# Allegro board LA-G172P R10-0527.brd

Outline 293.2 x 85.85 mm; copper layers: TOP, GND1, IN1, GND2, VCC, IN2, GND3, IN3, GND4, BOTTOM. Coordinates in mm from the lower left corner of the outline.

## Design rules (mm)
net group CB: nets CBN CBP
net group CHG_CSI: nets CHG_CSIN CHG_CSIP
net group CHG_CSO: nets CHG_CSON CHG_CSOP
net group CLK_PCIE_P1: nets CLK_PCIE_N1 CLK_PCIE_P1
net group CLK_PCIE_P1_R: nets CLK_PCIE_N1_R CLK_PCIE_P1_R
net group CLK_SMB: nets CLK_SMB DAT_SMB
net group CLK_TP_SIO_I2C_DAT: nets CLK_TP_SIO_I2C_DAT DAT_TP_SIO_I2C_CLK
net group DDR_A_CLK: nets DDR_A_CLK DDR_A_CLK#
net group DDR_B_CLK: nets DDR_B_CLK DDR_B_CLK#
net group DDR_C_CLK: nets DDR_C_CLK DDR_C_CLK#
net group DDR_C_DQS0: nets DDR_C_DQS0 DDR_C_DQS#0
net group DDR_C_DQS1: nets DDR_C_DQS1 DDR_C_DQS#1
net group DDR_C_DQS2: nets DDR_C_DQS2 DDR_C_DQS#2
net group DDR_C_DQS3: nets DDR_C_DQS3 DDR_C_DQS#3
net group DDR_D_CLK: nets DDR_D_CLK DDR_D_CLK#
net group DDR_D_DQS0: nets DDR_D_DQS0 DDR_D_DQS#0
net group DDR_D_DQS1: nets DDR_D_DQS1 DDR_D_DQS#1
net group DDR_D_DQS2: nets DDR_D_DQS2 DDR_D_DQS#2
net group DDR_D_DQS3: nets DDR_D_DQS3 DDR_D_DQS#3
net group DDRA_CKE: nets DDR_A_CKE0 DDR_A_CKE1
net group DDRA_CTL: nets DDR_A_CS#0 DDR_A_CS#1
net group DDRB_CKE: nets DDR_B_CKE0 DDR_B_CKE1
net group DDRB_CTL: nets DDR_B_CS#0 DDR_B_CS#1
net group DDRC_CKE: nets DDR_C_CKE0 DDR_C_CKE1
net group DDRC_CTL: nets DDR_C_CS#0 DDR_C_CS#1
net group DDRD_CKE: nets DDR_D_CKE0 DDR_D_CKE1
net group DDRD_CTL: nets DDR_D_CS#0 DDR_D_CS#1
net group DIFFPAIR50: nets I2C3_PD_R_CLK_R I2C3_PD_R_DAT_R
net group EDP_AUXP_CONN: nets EDP_AUXN_CONN EDP_AUXP_CONN
net group EDP_TXP0_CONN: nets EDP_TXN0_CONN EDP_TXP0_CONN
net group EDP_TXP1_CONN: nets EDP_TXN1_CONN EDP_TXP1_CONN
net group EDP_TXP2_CONN: nets EDP_TXN2_CONN EDP_TXP2_CONN
net group EDP_TXP3_CONN: nets EDP_TXN3_CONN EDP_TXP3_CONN
net group I2C1_PD_L_CLK: nets I2C1_PD_L_CLK I2C1_PD_L_DAT
net group I2C1_PD_R_CLK: nets I2C1_PD_R_CLK I2C1_PD_R_DAT
net group I2C1_SCK_TP: nets I2C1_SCK_TP I2C1_SDA_TP
net group I2C2_PD_L_CLK: nets I2C2_PD_L_CLK I2C2_PD_L_DAT
net group I2C2_PD_R_CLK: nets I2C2_PD_R_CLK I2C2_PD_R_DAT
net group I2C_3_SCL_UFCAM: nets I2C_3_SCL_UFCAM I2C_3_SDA_UFCAM
net group I2C_3_SCL_UFCAM_R: nets I2C_3_SCL_UFCAM_R I2C_3_SDA_UFCAM_R
net group IMVP_SMBCLK: nets IMVP_SMBCLK IMVP_SMBDAT
net group IMVP_SMBCLK_VR: nets IMVP_SMBCLK_VR IMVP_SMBDAT_VR
net group ISH_I2C0_SCL: nets ISH_I2C0_SCL ISH_I2C0_SDA
net group ISH_I2C1_SCL: nets ISH_I2C1_SCL ISH_I2C1_SDA
net group ISH_I2C1_SCL_R: nets ISH_I2C1_SCL_R ISH_I2C1_SDA_R
net group MIPI60_CFG_STB0_D: nets MIPI60_CFG_STB0_DN MIPI60_CFG_STB0_DP
net group MIPI60_CFG_STB1_D: nets MIPI60_CFG_STB1_DN MIPI60_CFG_STB1_DP
net group N20151664: nets N20151644 N20151664
net group PCH_DMIC_CLK12: nets PCH_DMIC_CLK12 PCH_DMIC_DATA12
net group PCIE_PRX_DTX_P13: nets PCIE_PRX_DTX_N13 PCIE_PRX_DTX_P13
net group PCIE_PRX_DTX_P14: nets PCIE_PRX_DTX_N14 PCIE_PRX_DTX_P14
net group PCIE_PTX_C_DRX_P13: nets PCIE_PTX_C_DRX_N13 PCIE_PTX_C_DRX_P13
net group PCIE_PTX_C_DRX_P14: nets PCIE_PTX_C_DRX_N14 PCIE_PTX_C_DRX_P14
net group PCIE_PTX_DRX_P13: nets PCIE_PTX_DRX_N13 PCIE_PTX_DRX_P13
net group PCIE_PTX_DRX_P14: nets PCIE_PTX_DRX_N14 PCIE_PTX_DRX_P14
net group PCIE_RCOMP: nets PCIE_RCOMPN PCIE_RCOMPP
net group PECI: nets PCH_PCIE_WAKE# PCIE_WAKE#
net group REM_DIODE1: nets REM_DIODE1_N REM_DIODE1_P
net group REM_DIODE4: nets REM_DIODE4_N REM_DIODE4_P
net group SMB_CLK: nets SMB_CLK SMB_DATA
net group SMB_CLK_MIPI60: nets SMB_CLK_MIPI60 SMB_DATA_MIPI60
net group SML0_SMBCLK: nets SML0_SMBCLK SML0_SMBDATA
net group SML0B_SMBCLK: nets SML0B_SMBCLK SML0B_SMBDATA
net group SML1_SMBCLK: nets SML1_SMBCLK SML1_SMBDATA
net group SML1_SMBCLK_R: nets SML1_SMBCLK_R SML1_SMBDATA_R
net group TAP_SMBCLK: nets TAP_SMBCLK TAP_SMBDAT
net group TAP_SMBCLK_R: nets TAP_SMBCLK_R TAP_SMBDAT_R
net group TBT_0_TRX_C_RD_DTX_0: nets TBT_0_TRX_C_RD_DTX_N0 TBT_0_TRX_C_RD_DTX_P0
net group TBT_0_TRX_C_RD_DTX_1: nets TBT_0_TRX_C_RD_DTX_N1 TBT_0_TRX_C_RD_DTX_P1
net group TBT_0_TRX_RT_DTX_0: nets TBT_0_TRX_RT_DTX_N0 TBT_0_TRX_RT_DTX_P0
net group TBT_0_TRX_RT_DTX_1: nets TBT_0_TRX_RT_DTX_N1 TBT_0_TRX_RT_DTX_P1
net group TBT_0_TTX_C_RD_DRX_0: nets TBT_0_TTX_C_RD_DRX_N0 TBT_0_TTX_C_RD_DRX_P0
net group TBT_0_TTX_C_RD_DRX_1: nets TBT_0_TTX_C_RD_DRX_N1 TBT_0_TTX_C_RD_DRX_P1
net group TBT_0_TTX_CD_DRX_0: nets TBT_0_TTX_CD_DRX_N0 TBT_0_TTX_CD_DRX_P0
net group TBT_0_TTX_CD_DRX_1: nets TBT_0_TTX_CD_DRX_N1 TBT_0_TTX_CD_DRX_P1
net group TBT_2_TRX_C_RD_DTX_0: nets TBT_2_TRX_C_RD_DTX_N0 TBT_2_TRX_C_RD_DTX_P0
net group TBT_2_TRX_C_RD_DTX_1: nets TBT_2_TRX_C_RD_DTX_N1 TBT_2_TRX_C_RD_DTX_P1
net group TBT_2_TRX_RT_DTX_P0: nets TBT_2_TRX_RT_DTX_N0 TBT_2_TRX_RT_DTX_P0
net group TBT_2_TRX_RT_DTX_P1: nets TBT_2_TRX_RT_DTX_N1 TBT_2_TRX_RT_DTX_P1
net group TBT_2_TTX_C_RD_DRX_0: nets TBT_2_TTX_C_RD_DRX_N0 TBT_2_TTX_C_RD_DRX_P0
net group TBT_2_TTX_C_RD_DRX_1: nets TBT_2_TTX_C_RD_DRX_N1 TBT_2_TTX_C_RD_DRX_P1
net group TBT_2_TTX_CD_DRX_P1: nets TBT_2_TTX_CD_DRX_N1 TBT_2_TTX_CD_DRX_P1
net group TBT_L_SMBCLK: nets TBT_L_SMBCLK TBT_L_SMBDAT
net group TBT_R_SMBCLK: nets TBT_R_SMBCLK TBT_R_SMBDAT
net group TCRCOMP_D: nets TCRCOMP_DN TCRCOMP_DP
net group TS_I2C_SCL_R: nets TS_I2C_SCL_R TS_I2C_SDA_R
net group UPD_L_SMBCLK: nets UPD_L_SMBCLK UPD_L_SMBDAT
net group UPD_R_SMBCLK: nets UPD_R_SMBCLK UPD_R_SMBDAT
net group UPD_SMBCLK: nets UPD_SMBCLK UPD_SMBDAT
net group USB20_N10: nets USB20_N10 USB20_P10
net group USB20_N10_R: nets USB20_N10_R USB20_P10_R
net group WOV_DMIC_CLK0: nets WOV_DMIC_CLK0 WOV_DMIC_DATA0
net group 10: nets SPK_-OUT-L+ SPK_-OUT-L- SPK_-OUT-R+ SPK_-OUT-R- SPK_L+ SPK_L- SPK_R+ SPK_R- TBT_L_CC1 TBT_L_CC2 TBT_R_CC1 TBT_R_CC2
net group 12: nets DDR_DRAMRST# DDR_DRAMRST#_R H_CATERR# H_PROCHOT# H_PROCHOT#_R SD_CD# SD_CLK SD_CLK_L SD_CMD SD_CMD_L SD_D2 SD_D2_L SD_D3 SD_D3_L SD_LN0_M SD_LN0_P SD_LN1_M SD_LN1_P SD_RCLK_M SD_RCLK_M_L SD_RCLK_P SD_RCLK_P_L SD_REG2 SP7_SDWP
net group CLK_S: nets MEC_XTAL1 MEC_XTAL2 MEC_XTAL2_R PCH_RTCX1 PCH_RTCX2 PCH_RTCX2_R TBT_L_XTAL_25_IN TBT_L_XTAL_25_IN_R TBT_L_XTAL_25_OUT TBT_L_XTAL_25_OUT_R TBT_R_XTAL_25_IN TBT_R_XTAL_25_IN_R TBT_R_XTAL_25_OUT TBT_R_XTAL_25_OUT_R XTAL_38P4M_IN XTAL_38P4M_IN_CPU XTAL_38P4M_OUT XTAL_38P4M_OUT_CPU
net group CNV: nets CLK_CNV_PRX_DTX_N CLK_CNV_PRX_DTX_P CLK_CNV_PTX_DRX_N CLK_CNV_PTX_DRX_P CNV_PRX_DTX_N0 CNV_PRX_DTX_N1 CNV_PRX_DTX_P0 CNV_PRX_DTX_P1 CNV_PTX_DRX_N0 CNV_PTX_DRX_N1 CNV_PTX_DRX_P0 CNV_PTX_DRX_P1
net group CNV_S: nets CNV_BRI_PRX_DTX CNV_BRI_PRX_R_DTX CNV_BRI_PRX_R_DTX_R CNV_BRI_PTX_DRX CNV_BRI_PTX_R_DRX CNV_RGI_PRX_DTX CNV_RGI_PRX_R_DTX CNV_RGI_PTX_DRX CNV_RGI_PTX_R_DRX CNV_RGI_PTX_R_DRX_R
net group CRITICAL: nets SUSCLK
net group DDR_DQS: nets DDR_A_DQS0 DDR_A_DQS1 DDR_A_DQS2 DDR_A_DQS3 DDR_A_DQS#0 DDR_A_DQS#1 DDR_A_DQS#2 DDR_A_DQS#3 DDR_B_DQS0 DDR_B_DQS1 DDR_B_DQS2 DDR_B_DQS3 DDR_B_DQS#0 DDR_B_DQS#1 DDR_B_DQS#2 DDR_B_DQS#3
net group DDRA_CA: nets DDR_A_CA0 DDR_A_CA1 DDR_A_CA2 DDR_A_CA3 DDR_A_CA4 DDR_A_CA5
net group DDRA_D0: nets DDR_A_D0_0 DDR_A_D0_1 DDR_A_D0_2 DDR_A_D0_3 DDR_A_D0_4 DDR_A_D0_5 DDR_A_D0_6 DDR_A_D0_7
net group DDRA_D1: nets DDR_A_D1_0 DDR_A_D1_1 DDR_A_D1_2 DDR_A_D1_3 DDR_A_D1_4 DDR_A_D1_5 DDR_A_D1_6 DDR_A_D1_7
net group DDRA_D2: nets DDR_A_D2_0 DDR_A_D2_1 DDR_A_D2_2 DDR_A_D2_3 DDR_A_D2_4 DDR_A_D2_5 DDR_A_D2_6 DDR_A_D2_7
net group DDRA_D3: nets DDR_A_D3_0 DDR_A_D3_1 DDR_A_D3_2 DDR_A_D3_3 DDR_A_D3_4 DDR_A_D3_5 DDR_A_D3_6 DDR_A_D3_7
net group DDRB_CA: nets DDR_B_CA0 DDR_B_CA1 DDR_B_CA2 DDR_B_CA3 DDR_B_CA4 DDR_B_CA5
net group DDRB_D0: nets DDR_B_D0_0 DDR_B_D0_1 DDR_B_D0_2 DDR_B_D0_3 DDR_B_D0_4 DDR_B_D0_5 DDR_B_D0_6 DDR_B_D0_7
net group DDRB_D1: nets DDR_B_D1_0 DDR_B_D1_1 DDR_B_D1_2 DDR_B_D1_3 DDR_B_D1_4 DDR_B_D1_5 DDR_B_D1_6 DDR_B_D1_7
net group DDRB_D2: nets DDR_B_D2_0 DDR_B_D2_1 DDR_B_D2_2 DDR_B_D2_3 DDR_B_D2_4 DDR_B_D2_5 DDR_B_D2_6 DDR_B_D2_7
net group DDRB_D3: nets DDR_B_D3_0 DDR_B_D3_1 DDR_B_D3_2 DDR_B_D3_3 DDR_B_D3_4 DDR_B_D3_5 DDR_B_D3_6 DDR_B_D3_7
net group DDRC_CA: nets DDR_C_CA0 DDR_C_CA1 DDR_C_CA2 DDR_C_CA3 DDR_C_CA4 DDR_C_CA5
net group DDRC_D0: nets DDR_C_D0_0 DDR_C_D0_1 DDR_C_D0_2 DDR_C_D0_3 DDR_C_D0_4 DDR_C_D0_5 DDR_C_D0_6 DDR_C_D0_7
net group DDRC_D1: nets DDR_C_D1_0 DDR_C_D1_1 DDR_C_D1_2 DDR_C_D1_3 DDR_C_D1_4 DDR_C_D1_5 DDR_C_D1_6 DDR_C_D1_7
net group DDRC_D2: nets DDR_C_D2_0 DDR_C_D2_1 DDR_C_D2_2 DDR_C_D2_3 DDR_C_D2_4 DDR_C_D2_5 DDR_C_D2_6 DDR_C_D2_7
net group DDRC_D3: nets DDR_C_D3_0 DDR_C_D3_1 DDR_C_D3_2 DDR_C_D3_3 DDR_C_D3_4 DDR_C_D3_5 DDR_C_D3_6 DDR_C_D3_7
net group DDRD_CA: nets DDR_D_CA0 DDR_D_CA1 DDR_D_CA2 DDR_D_CA3 DDR_D_CA4 DDR_D_CA5
net group DDRD_D0: nets DDR_D_D0_0 DDR_D_D0_1 DDR_D_D0_2 DDR_D_D0_3 DDR_D_D0_4 DDR_D_D0_5 DDR_D_D0_6 DDR_D_D0_7
net group DDRD_D1: nets DDR_D_D1_0 DDR_D_D1_1 DDR_D_D1_2 DDR_D_D1_3 DDR_D_D1_4 DDR_D_D1_5 DDR_D_D1_6 DDR_D_D1_7
net group DDRD_D2: nets DDR_D_D2_0 DDR_D_D2_1 DDR_D_D2_2 DDR_D_D2_3 DDR_D_D2_4 DDR_D_D2_5 DDR_D_D2_6 DDR_D_D2_7
net group DDRD_D3: nets DDR_D_D3_0 DDR_D_D3_1 DDR_D_D3_2 DDR_D_D3_3 DDR_D_D3_4 DDR_D_D3_5 DDR_D_D3_6 DDR_D_D3_7
net group EDP: nets EDP_AUXN EDP_AUXP EDP_TXN0 EDP_TXN1 EDP_TXN2 EDP_TXN3 EDP_TXP0 EDP_TXP1 EDP_TXP2 EDP_TXP3
net group ESPI: nets ESPI_CLK ESPI_CLK_5105 ESPI_CS# ESPI_IO0 ESPI_IO0_R ESPI_IO1 ESPI_IO1_R ESPI_IO2 ESPI_IO2_R ESPI_IO3 ESPI_IO3_R ESPI_RESET#
net group HDA: nets HDA_BIT_CLK HDA_BIT_CLK_L HDA_SDIN0 HDA_SDOUT HDA_SDOUT_L HDA_SYNC HDA_SYNC_L
net group I2C: nets I2C3_PD_L_CLK_R I2C3_PD_L_DAT_R I2C_RT_L_SCL I2C_RT_L_SDA I2C_RT_R_SCL I2C_RT_R_SDA TS_I2C_SCL TS_I2C_SDA
net group MIPI: nets MCSI_E_CLKN MCSI_E_CLKP MCSI_E_DN0 MCSI_E_DP0
net group PCIE: nets PCIE_PRX_C_DTX_N3 PCIE_PRX_C_DTX_N9 PCIE_PRX_C_DTX_N10 PCIE_PRX_C_DTX_N11 PCIE_PRX_C_DTX_N12 PCIE_PRX_C_DTX_N16 PCIE_PRX_C_DTX_P3 PCIE_PRX_C_DTX_P9 PCIE_PRX_C_DTX_P10 PCIE_PRX_C_DTX_P11 PCIE_PRX_C_DTX_P12 PCIE_PRX_C_DTX_P16 PCIE_PRX_DTX_N3 PCIE_PRX_DTX_N9 PCIE_PRX_DTX_N10 PCIE_PRX_DTX_N11 PCIE_PRX_DTX_N12 PCIE_PRX_DTX_N16 PCIE_PRX_DTX_P3 PCIE_PRX_DTX_P9 PCIE_PRX_DTX_P10 PCIE_PRX_DTX_P11 PCIE_PRX_DTX_P12 PCIE_PRX_DTX_P16 PCIE_PTX_C_DRX_N3 PCIE_PTX_C_DRX_N9 PCIE_PTX_C_DRX_N10 PCIE_PTX_C_DRX_N11 PCIE_PTX_C_DRX_N12 PCIE_PTX_C_DRX_N16 PCIE_PTX_C_DRX_P3 PCIE_PTX_C_DRX_P9 PCIE_PTX_C_DRX_P10 PCIE_PTX_C_DRX_P11 PCIE_PTX_C_DRX_P12 PCIE_PTX_C_DRX_P16 PCIE_PTX_DRX_N3 PCIE_PTX_DRX_N9 PCIE_PTX_DRX_N10 PCIE_PTX_DRX_N11 PCIE_PTX_DRX_N12 PCIE_PTX_DRX_N16 PCIE_PTX_DRX_P3 PCIE_PTX_DRX_P9 PCIE_PTX_DRX_P10 PCIE_PTX_DRX_P11 PCIE_PTX_DRX_P12 PCIE_PTX_DRX_P16
net group PLAT_CLK: nets CLK_PCIE_N0 CLK_PCIE_N0_R CLK_PCIE_N2 CLK_PCIE_N2_R CLK_PCIE_N4 CLK_PCIE_N4_R CLK_PCIE_P0 CLK_PCIE_P0_R CLK_PCIE_P2 CLK_PCIE_P2_R CLK_PCIE_P4 CLK_PCIE_P4_R
net group PWR: nets +3.3V_EC_PLL +3VALWP +3VS_FP +3VS_TPM +5VALWP +EC_DEBUG_VCC +PECI_VREF +RTC_CELL_VBAT +RTCBATT +RTCVCC +VBATT +VR_CAP
net group RTC: nets PCH_RTCRST#
net group SMB: nets DMIC_CLK12 DMIC_DATA12 PBAT_CHARGER_SMBCLK PBAT_CHARGER_SMBDAT UPD_SMBCLK_Q UPD_SMBDAT_Q
net group SPI: nets PCH_SPI_CLK PCH_SPI_CLK_R PCH_SPI_CLK_TPM SPI_CLK_VROM0
net group SPI_5_15: nets PCH_SPI_CS0# PCH_SPI_CS0#_R PCH_SPI_CS1# PCH_SPI_CS2# PCH_SPI_CS2#_TPM PCH_SPI_IO2 PCH_SPI_IO2_R PCH_SPI_IO3 PCH_SPI_IO3_R PCH_SPI_SI PCH_SPI_SI_R PCH_SPI_SI_TPM PCH_SPI_SO PCH_SPI_SO_R PCH_SPI_SO_TPM SPI_IO2_VROM0 SPI_IO3_VROM0 SPI_SI_VROM0 SPI_SO_VROM0
net group TBT_CONN: nets TBT_0_TTX_C_DRX_N0 TBT_0_TTX_C_DRX_N1 TBT_0_TTX_C_DRX_P0 TBT_0_TTX_C_DRX_P1 TBT_2_TTX_C_DRX_N0 TBT_2_TTX_C_DRX_N1 TBT_2_TTX_C_DRX_P0 TBT_2_TTX_C_DRX_P1 TBT_2_TTX_CD_DRX_N0 TBT_2_TTX_CD_DRX_P0
net group TBT_SOC: nets TBT_0_DP_AUXN TBT_0_DP_AUXN_R TBT_0_DP_AUXP TBT_0_DP_AUXP_R TBT_0_TRX_DTX_N0 TBT_0_TRX_DTX_N1 TBT_0_TRX_DTX_P0 TBT_0_TRX_DTX_P1 TBT_0_TTX_DRX_N0 TBT_0_TTX_DRX_N1 TBT_0_TTX_DRX_P0 TBT_0_TTX_DRX_P1 TBT_2_DP_AUXN TBT_2_DP_AUXN_R TBT_2_DP_AUXP TBT_2_DP_AUXP_R TBT_2_TRX_DTX_N0 TBT_2_TRX_DTX_N1 TBT_2_TRX_DTX_P0 TBT_2_TRX_DTX_P1 TBT_2_TTX_DRX_N0 TBT_2_TTX_DRX_N1 TBT_2_TTX_DRX_P0 TBT_2_TTX_DRX_P1
net group THERMAL: nets REM_DIODE2_N REM_DIODE2_P REM_DIODE3_N REM_DIODE3_P
net group THERMTRIP: nets H_THERMTRIP#
net group USB2.0: nets SW_TBT_L_USB20_N1 SW_TBT_L_USB20_N1_R SW_TBT_L_USB20_N2 SW_TBT_L_USB20_N2_R SW_TBT_L_USB20_P1 SW_TBT_L_USB20_P1_R SW_TBT_L_USB20_P2 SW_TBT_L_USB20_P2_R SW_TBT_R_USB20_N1 SW_TBT_R_USB20_N1_R SW_TBT_R_USB20_N2 SW_TBT_R_USB20_N2_R SW_TBT_R_USB20_P1 SW_TBT_R_USB20_P1_R SW_TBT_R_USB20_P2 SW_TBT_R_USB20_P2_R USB20_N1 USB20_N5 USB20_N5_R USB20_N8 USB20_N9 USB20_P1 USB20_P5 USB20_P5_R USB20_P8 USB20_P9
net group USB3.0: nets USB3_PRX_DTX_N2 USB3_PRX_DTX_P2 USB3_PTX_C_DRX_N2 USB3_PTX_C_DRX_P2 USB3_PTX_DRX_N2 USB3_PTX_DRX_P2
nets with their own width: min track width 0.254; nets +1.8VS_AUDIO +3.3V_ALW_UE1 +3.3V_BAT_LDO +3.3V_TBT_L_ANA +3.3V_TBT_L_FLASH +3.3V_TBT_L_FLASH_R +3.3V_TBT_L_LC +3.3V_TBT_L_SX +3.3V_TBT_R_ANA +3.3V_TBT_R_FLASH +3.3V_TBT_R_FLASH_R +3.3V_TBT_R_LC +3.3V_TBT_R_SX +3.3VA_TBT_L +3.3VA_TBT_R +3V_1.8V_HDA +3V_NB_LID +3V_SPI +3VS_AUDIO +3VS_TS +AVDD1 +DVDD +DVDD_MIC +DVDDIO +SD_VDD2 +V1.05A_BYPASS +VCC1P05_OUTPUT_PLL +VCC1V8_TBT_L_LDO +VCC1V8_TBT_R_LDO +VCCA_CLKLDO_1P8 +VCCDPHY_1P24 +VCCDSW_1P05 +VCCIO_OUT +VCCLDOSTD_OUT_0P85 +VCCPRTC_3P3 +VSS_PLL LDO2_CAP LDO3_CAP N59074258
nets with their own width: min track width 0.297; nets N57957180 N57957195 N57957882 N73546395
nets with their own width: min track width 0.381; nets +3.3V_TBT_L +3.3V_TBT_R HPOL_CONN HPOR_CONN HPOUT-L HPOUT-L_L HPOUT-R HPOUT-R_L LINE2-L LINE2-R MIC2-VREFO-L MIC2-VREFO-R
nets with their own width: min track width 0.508; nets +0.6V_VDDQP +1.1V_MEM +1.8V_3.3V_ALW_VTR3 +1.8V_PRIM +1.8VS +3V_NB_LID_R +3V_PRIM +3VALW +3VALW_DSW +3VS +3VS_SSD +5VALW +5VALWB +5VS_AUDIO +CHG_SRC_20V +RTCVCC_R +SSD_PWR2P +SSD_PWR3P +V1.05A_MIPI60 +V1.05A_VREF_DEBUG +VCC3V3_TBT_L_LDO +VCC3V3_TBT_R_LDO +VIN_3V3_L_TBT +VIN_3V3_R_TBT +VNN_BYPASS B+ GND JUSBC1_GND N73891446
nets with their own width: min track width 0.762; nets +1.05V_VCCST +1.05V_VCCSTG +1.8V_MEM +LCDVDD +SD_VDD1 +TBT_L_SVR_IND +TBT_R_SVR_IND +VCC1.05_OUT_FET +VCC1.05_OUT_PCH +VCC_SFR_OC +VCCST_CPU +VCCSTG_CPU +VCCSTG_OUT +VCCSTG_OUT_LGC
nets with their own width: min track width 1.016; nets +0.9V_TBT_L_LVR +0.9V_TBT_L_SVR +0.9V_TBT_R_LVR +0.9V_TBT_R_SVR +5VBS +5VS +INV_PWR_SRC RING2 RING2_CONN SLEEVE SLEEVE_CONN
nets with their own width: min track width 1.27; nets +VDDQ_MEM
nets with their own width: min track width 1.524; nets +1.1V_MEMP +PVDD
nets with their own width: min track width 1.778; nets +0.6V_VDDQ +3V_5V_CAM_PWR +CAM_PWR
nets with their own width: min track width 2.032; nets +3.3VDX_SSD +3VS_CR +3VS_WLAN +SSD_PWR3 +SSD_PWR_3 +VCC1P8A
nets with their own width: min track width 3.048; nets +1.8V_1.2V_SSD +1.8V_1.2VDX_SSD +CHG_VIN_20V +SSD_PWR2
nets with their own width: min track width 3.556; nets +5VALW_L_TBT +5VALWB_R_TBT +TBT_VBUS_L +TBT_VBUS_L_PD +TBT_VBUS_R +TBT_VBUS_R_PD

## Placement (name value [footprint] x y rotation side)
C1  0.1U_0201_10V6K  [C_0201]  135.16 77.02 90 bottom
C2  0.1U_0201_10V6K  [C_0201]  135.73 77.02 90 bottom
C3  0.1U_0201_10V6K  [C_0201]  136.81 77.02 90 bottom
C4  0.1U_0201_10V6K  [C_0201]  137.38 77.02 90 bottom
C5  0.1U_0201_10V6K  [C_0201]  138.46 77.02 90 bottom
C6  0.1U_0201_10V6K  [C_0201]  139.03 77.02 90 bottom
C7  0.1U_0201_10V6K  [C_0201]  140.05 77.02 90 bottom
C8  0.1U_0201_10V6K  [C_0201]  140.62 77.02 90 bottom
C9  0.1U_0201_10V6K  [C_0201]  134.21 77.02 90 bottom
C10  0.1U_0201_10V6K  [C_0201]  133.64 77.02 90 bottom
C37  1U_0201_6.3V6M  [C_0201]  107.16 69.48 270 top
C38  0.1U_0201_10V6K  [C_0201]  106.74 71.86 0 top
C41  10U_0402_6.3V6M  [C_0402]  106.71 70.97 0 top
C46  0.1U_0201_10V6K  [C_0201]  126.33 83.37 90 bottom
C47  10U_0402_10V6M  [C_0402]  127.1 83.34 90 bottom
C48  33P_0402_50V8J  [C_0402]  127.99 83.34 90 bottom
C49  0.1U_0402_25V6  [C_0402]  98.08 71.14 90 top
C50  1U_0603_25V6K  [C_0603]  99.04 66.83 270 top
C52  0.1U_0402_25V6  [C_0402]  126.4 80.31 0 bottom
C58  0.1U_0402_25V6  [C_0402]  126.25 81.99 0 bottom
C87  0.1U_0402_25V6  [C_0402]  102.02 71.99 0 top
C92  2.2U_0201_6.3V6M  [C_0201]  206.66 61.25 0 bottom
C94  10U_0402_6.3V6M  [C_0402]  207.59 5.84 180 top
C95  0.1U_0201_10V6K  [C_0201]  207.4 6.58 180 top
C96  0.1U_0201_10V6K  [C_0201]  215.22 9.04 0 top
C97  0.1U_0201_10V6K  [C_0201]  212.19 4.46 270 top
C100  0.1U_0201_10V6K  [C_0201]  113.32 3.69 270 bottom
C112  1U_0201_6.3V6M  [C_0201]  177.34 11.15 180 top
C200  0.1U_0201_16V6K  [C_0201]  110.78 3.69 270 bottom
C216  1U_0201_6.3V6M  [C_0201]  205.99 11.87 90 top
C217  2200P_0402_25V7K  [C_0402]  203.55 15.01 90 top
C218  0.1U_0201_10V6K  [C_0201]  201.2 16.52 270 top
C220  0.1U_0201_16V6K  [C_0201]  117.76 3.69 270 bottom
C223  0.1U_0201_10V6K  [C_0201]  172.31 71.39 270 top
C224  2200P_0402_25V7K  [C_0402]  174.47 70.24 90 top
C227  1000P_0402_25V8J  [C_0402]  238.97 18.9 0 top
C229  1U_0201_6.3V6M  [C_0201]  241.24 18.74 180 top
C230  0.1U_0201_10V6K  [C_0201]  237.42 18.77 0 top
C233  0.1U_0201_10V6K  [C_0201]  175.52 71.86 180 top
C234  4700P_0402_16V7K  [C_0402]  67.15 13.38 270 top
C235  1U_0201_6.3V6M  [C_0201]  172.88 65.28 270 top
C237  2200P_0402_25V7K  [C_0402]  175.36 70.24 90 top
C240  1U_0201_6.3V6M  [C_0201]  176.63 65.42 270 top
C243  1U_0201_6.3V6M  [C_0201]  17.74 27.92 225 top
C244  1000P_0402_25V8J  [C_0402]  19.34 23.02 135 top
C245  3300P_0402_25V7K  [C_0402]  42.23 16.67 180 top
C246  1U_0201_10V6M  [C_0201]  45.54 14.64 180 top
C248  0.1U_0201_10V6K  [C_0201]  188.56 53.15 90 top
C252  1U_0201_6.3V6M  [C_0201]  195.13 51.54 0 top
C256  1U_0201_6.3V6M  [C_0201]  68.17 18.35 90 top
C276  0.1U_0201_10V6K  [C_0201]  68.13 11.15 0 top
C277  0.1U_0201_10V6K  [C_0201]  20.94 22.79 45 top
C278  0.1U_0201_10V6K  [C_0201]  41.27 15.47 0 top
C285  0.1U_0201_16V6K  [C_0201]  118.4 3.69 270 bottom
C418  0.1U_0201_10V6K  [C_0201]  128.72 77.99 270 bottom
C419  0.1U_0201_25V6K  [C_0201]  126.66 81.26 0 bottom
C420  0.1U_0201_25V6K  [C_0201]  128.72 83.59 90 bottom
C421  10U_0402_6.3V6M  [C_0402]  207.59 10.84 180 top
C422  0.1U_0201_10V6K  [C_0201]  207.42 10.08 180 top
C451  0.1U_0201_10V6K  [C_0201]  128.45 81.31 180 bottom
C452  15P_0201_50V8J  [C_0201]  128.45 81.89 180 bottom
C453  0.1U_0201_10V6K  [C_0201]  216.25 6.79 270 top
C454  12P_0201_50V8J  [C_0201]  206.42 8.98 270 top
C455  68P_0201_50V8J  [C_0201]  205.79 8.98 270 top
C622  0.1U_0201_16V6K  [C_0201]  247.77 10.82 90 top
C625  10U_0402_10V6M  [C_0402]  163.67 75.59 0 bottom
C628  10U_0402_10V6M  [C_0402]  247.01 10.92 90 top
C635  0.1U_0201_16V6K  [C_0201]  163.74 76.35 0 bottom
C640  1U_0201_6.3V6M  [C_0201]  248.36 10.82 90 top
C750  680P_0402_50V7K  [C_0402]  189.07 41.74 90 top
C760  0.33U_0201_6.3V6M  [C_0201]  107.83 67.54 180 top
C761  0.33U_0201_6.3V6M  [C_0201]  188.09 41.5 180 top
C800  0.1U_0201_10V6K  [C_0201]  270.1 24.03 180 top
C801  0.1U_0201_10V6K  [C_0201]  264.05 18.38 0 top
C1040  1U_0201_6.3V6M  [C_0201]  181.13 15.21 270 top
C1124  10U_0603_25V6M  [C_0603]  68.61 8.74 180 top
C1125  10U_0603_25V6M  [C_0603]  235.49 10.96 270 top
C1131  0.1U_0402_25V6K~D  [C_0402]  178.1 16.17 180 top
C1132  22P_0402_50V8J  [C_0402]  181.15 18.26 180 top
C1223  10U_0603_25V6M  [C_0603]  101.9 70.93 0 top
C1224  0.1U_0402_25V7K  [C_0402]  97.9 68.32 90 top
C1226  680P_0201_25V7K  [C_0201]  255.62 10.86 90 top
C1229  680P_0201_25V7K  [C_0201]  257.02 10.86 90 top
C1387  10U_0402_6.3V6M  [C_0402]  215.45 9.8 90 top
C1467  2200P_0402_25V7K  [C_0402]  204.44 15.01 90 top
C1468  0.1U_0201_10V6K  [C_0201]  208.54 14.12 90 top
C1469  1U_0201_6.3V6M  [C_0201]  202.79 10.3 270 top
C1539  0.1U_0201_10V6K  [C_0201]  167.04 81.04 270 bottom
C1540  0.1U_0201_10V6K  [C_0201]  166.4 81.04 270 bottom
C1544  0.1U_0201_10V6K  [C_0201]  106.59 14.54 90 bottom
C1675  0.1U_0201_10V6K  [C_0201]  197.11 27.28 180 top
C1676  0.01U_0402_16V7K  [C_0402]  200.64 27.28 180 top
C1678  1U_0201_6.3V6M  [C_0201]  204.6 25.04 180 top
C1681  0.1U_0201_10V6K  [C_0201]  212.69 44.21 270 top
C1683  0.01U_0402_16V7K  [C_0402]  217.38 48.93 0 top
C1684  1U_0201_6.3V6M  [C_0201]  214.6 43.37 90 top
C1686  10P_0201_25V8  [C_0201]  201.39 45.78 90 bottom
C1687  10P_0201_25V8  [C_0201]  200.76 45.78 90 bottom
C1688  0.1U_0201_6.3V6K  [C_0201]  202.31 33.12 0 bottom
C1689  0.1U_0201_6.3V6K  [C_0201]  200.12 45.78 90 bottom
C1690  1U_0201_6.3V6K  [C_0201]  202.31 32.49 0 bottom
C1691  1U_0201_6.3V6K  [C_0201]  202.31 31.85 0 bottom
C1695  10P_0201_25V8  [C_0201]  203.64 36.42 0 bottom
C1696  10P_0201_25V8  [C_0201]  202.66 37.27 90 bottom
C1697  0.1U_0201_6.3V6K  [C_0201]  203.64 35.79 0 bottom
C1698  0.1U_0201_6.3V6K  [C_0201]  201.39 37.27 90 bottom
C1699  1U_0201_6.3V6K  [C_0201]  200.76 37.27 90 bottom
C1700  1U_0201_6.3V6K  [C_0201]  200.12 37.27 90 bottom
C1704  0.1U_0201_6.3V6K  [C_0201]  202.03 37.27 90 bottom
C1705  0.1U_0201_6.3V6K  [C_0201]  203.64 35.15 0 bottom
C1706  1U_0201_6.3V6K  [C_0201]  197.75 35.47 180 bottom
C1707  1U_0201_6.3V6K  [C_0201]  197.75 36.1 180 bottom
C1714  10P_0201_25V8  [C_0201]  203.77 42.65 0 bottom
C1715  10P_0201_25V8  [C_0201]  197.62 41.38 180 bottom
C1716  0.1U_0201_6.3V6K  [C_0201]  203.77 42.01 0 bottom
C1717  0.1U_0201_6.3V6K  [C_0201]  202.03 43.75 90 bottom
C1718  0.1U_0201_6.3V6K  [C_0201]  203.77 41.38 0 bottom
C1719  0.1U_0201_6.3V6K  [C_0201]  198.91 43.75 90 bottom
C1720  1U_0201_6.3V6K  [C_0201]  197.62 42.65 180 bottom
C1721  1U_0201_6.3V6K  [C_0201]  199.55 43.75 90 bottom
C1722  1U_0201_6.3V6K  [C_0201]  202.6 43.75 90 bottom
C1723  1U_0201_6.3V6K  [C_0201]  197.62 42.01 180 bottom
C2990  1U_0201_6.3V6M  [C_0201]  60.87 19.75 90 top
C3011  1U_0201_6.3V6M  [C_0201]  171.77 55.79 180 top
C4180  15P_0201_25V8J  [C_0201]  248.94 10.82 90 top
C4181  0.1U_0402_25V6K~D  [C_0402]  69.31 5.99 90 top
C4182  0.1U_0402_25V6K~D  [C_0402]  234.41 10.59 270 top
C4183  100P_0201_50V8J  [C_0201]  60.36 18.41 90 top
C4186  0.1U_0201_10V6K  [C_0201]  60.93 18.41 90 top
C4189  2200P_0402_25V7K  [C_0402]  190.22 53.31 180 top
C4195  33P_0201_50V8J  [C_0201]  111.94 18.71 0 top
C4197  10U_0402_10V6M  [C_0402]  170.58 71.6 0 top
C4198  0.1U_0201_10V6K  [C_0201]  170.68 72.36 0 top
C4199  1U_0201_6.3V6M  [C_0201]  173.45 65.28 270 top
C4201  0.1U_0201_10V6K  [C_0201]  190.34 50.61 90 top
C4202  0.1U_0201_10V6K  [C_0201]  190.34 47.26 270 top
C4203  0.1U_0201_10V6K  [C_0201]  170.82 18.26 180 top
C4204  1U_0201_10V6M  [C_0201]  98.05 4.61 180 top
C4205  2200P_0402_25V7K  [C_0402]  94.66 6.83 180 top
C4207  0.1U_0201_10V6K  [C_0201]  93.4 4.04 0 top
C4209  470P_0402_50V7K  [C_0402]  189.9 15.54 270 top
C4210  0.1U_0201_10V6K  [C_0201]  188.86 17.75 180 top
C4211  1U_0201_6.3V6M  [C_0201]  187.42 11.57 270 top
C4212  1U_0201_10V6M  [C_0201]  270.49 19.33 90 top
C4213  220P_0402_50V8K  [C_0402]  265.31 20.53 180 top
C4216  1U_0201_6.3V6M  [C_0201]  264.47 21.91 270 top
C4217  10U_0402_10V6M  [C_0402]  270.26 23.2 180 top
C4221  0.1U_0201_16V6K  [C_0201]  243.76 10.88 90 top
C4222  10U_0402_10V6M  [C_0402]  244.52 10.84 90 top
C4227  1U_0402_25V6K  [C_0402]  271.29 12.36 270 top
C4230  0.1U_0201_10V6K  [C_0201]  218.07 7.4 180 top
C4231  1U_0201_10V6M  [C_0201]  170.95 68.2 180 top
CA9  330P_0201_50V7K  [C_0201]  32.42 20.89 90 top
CA10  10U_0603_6.3V6M  [C_0603]  28.23 23.47 0 top
CA11  330P_0201_50V7K  [C_0201]  31.85 20.89 90 top
CA12  10U_0603_6.3V6M  [C_0603]  25.81 23.47 0 top
CA13  100P_0201_25V7K  [C_0201]  23.76 21.82 180 top
CA14  0.1U_0201_10V6K  [C_0201]  24.44 20.55 0 top
CA15  10U_0402_10V6M  [C_0402]  28.86 21.17 90 top
CA17  2.2U_0201_10V6K  [C_0201]  26.26 21.09 270 top
CA18  2.2U_0603_10V7K  [C_0603]  33.4 21.12 330 top
CA19  10U_0402_10V6M  [C_0402]  37.05 17.55 90 top
CA20  4.7U_0402_10V6M  [C_0402]  25.56 19.8 270 top
CA21  2.2U_0603_10V7K  [C_0603]  36.88 19.54 170 top
CA22  10U_0402_10V6M  [C_0402]  24.04 17.74 90 top
CA23  0.1U_0201_10V6K  [C_0201]  24.8 17.65 90 top
CA24  0.1U_0201_10V6K  [C_0201]  35.15 17.08 90 top
CA25  10U_0402_10V6M  [C_0402]  24.18 13.88 180 top
CA26  0.1U_0201_10V6K  [C_0201]  23.82 16.48 180 top
CA29  10U_0402_10V6M  [C_0402]  35.91 16.66 90 top
CA30  0.1U_0201_10V6K  [C_0201]  23.82 15.85 180 top
CA31  10U_0402_10V6M  [C_0402]  24.18 14.77 180 top
CA32  10U_0402_10V6M  [C_0402]  35.26 15.72 0 top
CA33  0.1U_0201_10V6K  [C_0201]  30.66 11.09 0 top
CA36  0.1U_0201_10V6K  [C_0201]  35.28 14.87 270 top
CA37  22P_0201_25V8  [C_0201]  34.2 13.66 270 top
CA38  10U_0402_6.3V6M  [C_0402]  36.04 14.78 270 top
CA39  10U_0402_6.3V6M  [C_0402]  30.83 10.37 270 top
CA40  0.1U_0201_10V6K  [C_0201]  25.98 11.85 180 top
CA44  1000P_0201_25V7K  [C_0201]  11.82 6.52 0 bottom
CA45  1000P_0201_25V7K  [C_0201]  13.54 6.52 0 bottom
CA46  0.22U_0201_6.3V6M  [C_0201]  21.9 21.82 0 top
CA47  0.22U_0201_6.3V6M  [C_0201]  22.49 20.55 180 top
CA48  0.22U_0201_6.3V6M  [C_0201]  23.76 21.18 180 top
CA49  1000P_0201_25V7K  [C_0201]  10.11 6.52 0 bottom
CA50  1000P_0201_25V7K  [C_0201]  8.31 6.51 0 bottom
CA51  10U_0402_10V6M  [C_0402]  35.2 18.52 0 top
CA52  0.1U_0201_10V6K  [C_0201]  21.53 12.99 180 top
CA53  10U_0402_10V6M  [C_0402]  21.57 12.23 180 top
CA54  0.1U_0201_10V6K  [C_0201]  30.66 11.66 0 top
CA55  1U_0201_6.3V6M  [C_0201]  29.14 11.34 0 top
CA57  10P_0201_50V8J  [C_0201]  33.52 11.97 0 top
CA58  330P_0201_50V7K  [C_0201]  9.97 73.95 180 bottom
CA59  330P_0201_50V7K  [C_0201]  7.82 73.95 180 bottom
CA60  330P_0201_50V7K  [C_0201]  14.2 70.08 0 top
CA61  330P_0201_50V7K  [C_0201]  7.24 74.53 90 bottom
CA62  330P_0201_50V7K  [C_0201]  9.29 75.22 270 bottom
CA63  330P_0201_50V7K  [C_0201]  11.38 74.06 135 bottom
CA64  33P_0201_50V8J  [C_0201]  33.52 11.09 0 top
CA78  0.1U_0402_10V7K  [C_0402]  21.99 57.44 0 top
CA79  0.1U_0402_10V7K  [C_0402]  20.66 53.83 315 top
CA80  0.1U_0402_10V7K  [C_0402]  22.88 19.79 0 top
CA81  0.1U_0402_10V7K  [C_0402]  37.5 15.77 90 top
CA82  0.1U_0402_10V7K  [C_0402]  19.2 30.9 0 top
CA83  0.1U_0402_10V7K  [C_0402]  15.58 67.34 45 top
CA84  330P_0201_50V7K  [C_0201]  7.23 75.71 0 bottom
CA85  330P_0201_50V7K  [C_0201]  13.35 72.62 180 top
CC1  0.1U_0201_10V6K  [C_0201]  171.08 16.23 180 top
CC17  1U_0201_6.3V6M  [C_0201]  165.77 81.04 270 bottom
CC23  0.1U_0201_10V6K  [C_0201]  176.82 38.31 90 top
CC30  0.1U_0201_10V6K  [C_0201]  176.88 37.95 0 bottom
CC77  0.1U_0201_10V6K  [C_0201]  185.35 32.36 0 top
CC129  10U_0402_10V6M  [C_0402]  153.13 21.89 270 top
CC130  1U_0201_6.3V6K  [C_0201]  148.56 50.39 0 top
CC131  1U_0201_6.3V6K  [C_0201]  143.68 50.39 0 top
CC132  1U_0201_6.3V6K  [C_0201]  150.21 49.97 90 top
CC133  1U_0201_6.3V6K  [C_0201]  145.87 50.39 0 top
CC134  1U_0201_6.3V6K  [C_0201]  141.41 50.39 0 top
CC135  1U_0201_6.3V6K  [C_0201]  150.85 49.97 90 top
CC136  10U_0402_10V6M  [C_0402]  139.34 50.39 0 top
CC137  10U_0402_10V6M  [C_0402]  159.93 51.59 90 top
CC138  10U_0402_10V6M  [C_0402]  133.37 50.39 0 top
CC139  10U_0402_10V6M  [C_0402]  137.71 50.39 180 top
CC140  10U_0402_10V6M  [C_0402]  156.56 51.46 90 top
CC141  22U_0603_6.3V6M  [C_0603]  153.83 52.17 0 top
CC142  22U_0603_6.3V6M  [C_0603]  134.02 52.17 180 top
CC144  1U_0201_6.3V6M  [C_0201]  159.61 50.1 90 top
CC145  1U_0201_6.3V6M  [C_0201]  158.97 50.1 90 top
CC147  1U_0201_6.3V6M  [C_0201]  157.23 22.07 180 top
CC148  1U_0201_6.3V6M  [C_0201]  157.23 21.44 180 top
CC153  1U_0201_6.3V6M  [C_0201]  155.38 22.07 0 top
CC154  1U_0201_6.3V6M  [C_0201]  155.38 21.44 0 top
CC155  1U_0201_6.3V6M  [C_0201]  154.69 22.07 180 top
CC156  1U_0201_6.3V6M  [C_0201]  154.69 21.44 180 top
CC164  10P_0201_25V8  [C_0201]  181.24 39.85 180 top
CC167  2.2P_0201_25V  [C_0201]  178.75 39.6 0 top
CC168  2.2P_0201_25V  [C_0201]  177.39 38.9 270 top
CC170  1U_0201_6.3V6M  [C_0201]  177.32 35.94 90 bottom
CC171  0.1U_0201_10V6K  [C_0201]  176.75 35.94 90 bottom
CC173  1U_0201_6.3V6M  [C_0201]  176.52 33.09 270 bottom
CC174  1U_0201_6.3V6M  [C_0201]  182.91 33.34 90 bottom
CC175  1U_0201_6.3V6M  [C_0201]  183.55 33.34 90 bottom
CC176  47U_0603_6.3V6M  [C_0603]  179.36 36.93 0 top
CC177  1U_0201_6.3V6M  [C_0201]  177.45 31.75 90 top
CC180  1U_0201_6.3V6M  [C_0201]  176.88 39.13 270 bottom
CC181  0.1U_0201_10V6K  [C_0201]  176.88 39.75 90 bottom
CC182  1U_0201_6.3V6M  [C_0201]  177.52 39.75 90 bottom
CC183  1U_0201_6.3V6M  [C_0201]  176.84 41.88 0 bottom
CC184  4.7U_0201_6.3V6M  [C_0201]  176.79 39.61 0 top
CC185  1U_0201_6.3V6K  [C_0201]  177.35 42.77 0 top
CC188  10U_0402_10V6M  [C_0402]  152.24 21.89 270 top
CC189  1U_0201_6.3V6M  [C_0201]  158.34 50.1 90 top
CC191  1U_0201_6.3V6M  [C_0201]  133.99 40.8 0 bottom
CC260  1U_0201_6.3V6K  [C_0201]  176.77 42.77 270 top
CC308  22U_0603_6.3V6M  [C_0603]  151.1 22.01 270 top
CC386  1U_0201_6.3V6M  [C_0201]  147.8 16.18 270 top
CC387  22U_0603_6.3V6M  [C_0603]  198.09 26.33 270 top
CC388  22U_0603_6.3V6M  [C_0603]  196.82 26.33 270 top
CC389  22U_0603_6.3V6M  [C_0603]  193.77 17.31 0 top
CC390  22U_0603_6.3V6M  [C_0603]  193.77 18.52 0 top
CC391  22U_0603_6.3V6M  [C_0603]  211.74 44.74 270 top
CC392  22U_0603_6.3V6M  [C_0603]  210.47 44.74 270 top
CC394  0.1U_0201_10V6K  [C_0201]  170.49 61.7 0 top
CC395  1U_0201_6.3V6M  [C_0201]  107.7 50.84 0 top
CC511  0.1U_0402_25V6  [C_0402]  214.08 19.21 0 top
CC620  0.1U_0201_10V6K  [C_0201]  189.45 30.54 90 top
CC621  0.1U_0201_10V6K  [C_0201]  111.82 18.9 0 bottom
CC622  0.1U_0201_10V6K  [C_0201]  180.01 40.41 270 top
CC625  0.1U_0201_10V6K  [C_0201]  182.53 39 270 top
CC629  1U_0201_6.3V6M  [C_0201]  135.61 14.45 0 top
CC632  0.1U_0201_10V6K  [C_0201]  150.76 19.66 180 top
CC633  0.1U_0201_10V6K  [C_0201]  155.48 19.63 0 top
CC638  1U_0201_6.3V6M  [C_0201]  131.69 14.83 180 top
CC643  12P_0201_25V8J  [C_0201]  167.06 60.93 0 top
CC644  12P_0201_25V8J  [C_0201]  136.75 51.62 90 top
CC645  12P_0201_25V8J  [C_0201]  136.11 51.62 90 top
CC646  2.2P_0201_25V8C  [C_0201]  167.06 61.57 0 top
CC647  2.2P_0201_25V8C  [C_0201]  151.99 51.75 90 top
CC648  2.2P_0201_25V8C  [C_0201]  152.62 51.75 90 top
CC649  100P_0201_50V8J  [C_0201]  170.82 20.23 180 top
CC650  100P_0201_50V8J  [C_0201]  157.23 20.8 180 top
CC651  0.1U_0201_10V6K  [C_0201]  184.75 33.22 270 top
CC652  0.1U_0201_10V6K  [C_0201]  173.71 54.24 270 top
CC653  0.1U_0201_10V6K  [C_0201]  177.08 51.57 270 top
CC654  27P_0201_25V8  [C_0201]  174.98 54.96 270 bottom
CC655  33P_0201_50V8J  [C_0201]  169.77 36.71 270 bottom
CC656  33P_0201_50V8J  [C_0201]  170.4 36.13 90 bottom
CC657  33P_0201_50V8J  [C_0201]  172.94 34.9 90 bottom
CC658  33P_0201_50V8J  [C_0201]  161.77 49.97 270 bottom
CC659  33P_0201_50V8J  [C_0201]  165.2 44.05 90 bottom
CC660  12P_0201_25V8J  [C_0201]  138.27 51.62 90 top
CC661  12P_0201_25V8J  [C_0201]  153.96 70.55 90 top
CC662  12P_0201_25V8J  [C_0201]  150.46 51.75 90 top
CC663  2.2P_0201_25V8C  [C_0201]  138.91 51.62 90 top
CC664  2.2P_0201_25V8C  [C_0201]  151.1 51.75 90 top
CC665  2.2P_0201_25V8C  [C_0201]  154.59 70.55 90 top
CC666  0.1U_0201_10V6K  [C_0201]  155.38 20.8 0 top
CC667  0.1U_0201_10V6K  [C_0201]  154.69 20.8 180 top
CC668  0.1U_0201_10V6K  [C_0201]  150.21 21.35 270 top
CC707  0.1U_0402_10V7K  [C_0402]  93.89 65.05 90 top
CC721  0.1U_0201_10V6K  [C_0201]  108.01 46.2 0 top
CC727  2.2P_0201_50V8B  [C_0201]  164.5 45.92 270 bottom
CC735  0.1U_0201_25V6K  [C_0201]  130.33 22.11 270 top
CC736  0.1U_0201_25V6K  [C_0201]  130.91 22.11 270 top
CC737  0.1U_0201_25V6K  [C_0201]  132.14 25.18 0 bottom
CC738  0.1U_0201_25V6K  [C_0201]  126.52 21.16 270 top
CC739  0.1U_0201_25V6K  [C_0201]  124.56 21.16 270 top
CC740  0.1U_0201_10V6K  [C_0201]  121.24 59.03 0 top
CD3  10U_0402_10V6M  [C_0402]  115.03 70.57 90 top
CD4  10U_0402_10V6M  [C_0402]  129.26 52.37 270 top
CD5  10U_0402_10V6M  [C_0402]  130.02 70.56 90 top
CD6  10U_0402_10V6M  [C_0402]  115.98 52.56 270 top
CD7  10U_0402_10V6M  [C_0402]  153.64 63.55 270 top
CD8  10U_0402_10V6M  [C_0402]  121.38 64.11 0 top
CD9  10U_0402_10V6M  [C_0402]  106.95 65.25 270 top
CD10  10U_0402_10V6M  [C_0402]  136.88 64.82 270 top
CD11  10U_0402_10V6M  [C_0402]  136.94 57.9 270 top
CD12  10U_0402_10V6M  [C_0402]  153.68 66.91 90 top
CD13  1U_0201_10V6M  [C_0201]  108.24 65.06 90 top
CD14  1U_0201_10V6M  [C_0201]  108.43 57.42 270 top
CD15  1U_0201_10V6M  [C_0201]  121.44 57.89 270 top
CD16  1U_0201_10V6M  [C_0201]  121.38 64.88 90 top
CD17  1U_0201_10V6M  [C_0201]  108.41 61.67 180 top
CD18  1U_0201_10V6M  [C_0201]  108.41 62.28 180 top
CD19  1U_0201_10V6M  [C_0201]  115.22 52.65 270 top
CD20  1U_0201_10V6M  [C_0201]  121.28 60.49 90 top
CD21  1U_0201_10V6M  [C_0201]  121.29 62.5 90 top
CD22  1U_0201_10V6M  [C_0201]  114.27 70.55 90 top
CD23  1U_0201_10V6M  [C_0201]  107.84 56.2 270 top
CD24  1U_0201_10V6M  [C_0201]  108.39 66.31 90 top
CD25  1U_0201_10V6M  [C_0201]  107.79 66.29 90 top
CD26  1U_0201_10V6M  [C_0201]  108.41 56.21 270 top
CD27  2.2P_0201_50V8B  [C_0201]  114.08 52.34 270 top
CD28  2.2P_0201_50V8B  [C_0201]  123.9 52.56 270 top
CD29  1U_0201_10V6M  [C_0201]  123.29 57.89 270 top
CD30  1U_0201_10V6M  [C_0201]  136.16 57.97 270 top
CD31  1U_0201_10V6M  [C_0201]  136.11 64.87 270 top
CD32  1U_0201_10V6M  [C_0201]  123.32 66.14 180 top
CD33  1U_0201_10V6M  [C_0201]  123.29 61.25 270 top
CD34  1U_0201_10V6M  [C_0201]  123.29 61.86 90 top
CD35  1U_0201_10V6M  [C_0201]  129.18 70.45 90 top
CD36  1U_0201_10V6M  [C_0201]  128.42 52.59 270 top
CD37  1U_0201_10V6M  [C_0201]  136.34 61.09 0 top
CD38  1U_0201_10V6M  [C_0201]  136.34 61.72 0 top
CD39  1U_0201_10V6M  [C_0201]  123.29 56.13 90 top
CD40  1U_0201_10V6M  [C_0201]  123.31 66.95 180 top
CD41  1U_0201_10V6M  [C_0201]  121.38 66.67 90 top
CD42  1U_0201_10V6M  [C_0201]  136.18 56.2 90 top
CD43  2.2P_0201_50V8B  [C_0201]  127.16 52.59 270 top
CD44  2.2P_0201_50V8B  [C_0201]  126.59 52.59 270 top
CD45  12P_0201_50V8J  [C_0201]  114.65 52.34 270 top
CD46  12P_0201_50V8J  [C_0201]  123.29 52.56 270 top
CD47  12P_0201_50V8J  [C_0201]  127.73 52.59 270 top
CD48  12P_0201_50V8J  [C_0201]  126.02 52.59 270 top
CD49  12P_0201_50V8J  [C_0201]  154.02 53.15 90 top
CD50  12P_0201_50V8J  [C_0201]  167 54.96 0 top
CD51  1U_0201_10V6M  [C_0201]  153.35 57 0 top
CD52  1U_0201_10V6M  [C_0201]  140.22 57.89 180 top
CD53  1U_0201_10V6M  [C_0201]  140.22 65 180 top
CD54  1U_0201_10V6M  [C_0201]  153.33 65.58 0 top
CD55  1U_0201_10V6M  [C_0201]  144.84 51.54 0 top
CD56  1U_0201_10V6M  [C_0201]  153.93 59.6 180 top
CD57  1U_0201_10V6M  [C_0201]  146.57 70.71 180 top
CD58  1U_0201_10V6M  [C_0201]  140.22 62.97 180 top
CD59  1U_0201_10V6M  [C_0201]  140.22 60.55 180 top
CD60  1U_0201_10V6M  [C_0201]  153.35 69.7 0 top
CD61  1U_0201_10V6M  [C_0201]  144.53 70.71 180 top
CD62  1U_0201_10V6M  [C_0201]  148.98 70.71 180 top
CD63  1U_0201_10V6M  [C_0201]  143.44 52.55 0 top
CD64  1U_0201_10V6M  [C_0201]  149.16 52.42 0 top
CD65  2.2P_0201_50V8B  [C_0201]  140.22 56.11 180 top
CD66  2.2P_0201_50V8B  [C_0201]  153.26 53.15 90 top
CD67  1U_0201_10V6M  [C_0201]  153.93 66.19 180 top
CD68  1U_0201_10V6M  [C_0201]  167.06 57.12 0 top
CD69  1U_0201_10V6M  [C_0201]  153.35 56.36 0 top
CD70  1U_0201_10V6M  [C_0201]  167 65.63 0 top
CD71  1U_0201_10V6M  [C_0201]  167.06 62.77 0 top
CD72  1U_0201_10V6M  [C_0201]  167.06 62.2 0 top
CD73  1U_0201_10V6M  [C_0201]  153.35 69.11 0 top
CD74  1U_0201_10V6M  [C_0201]  153.93 59.03 180 top
CD75  1U_0201_10V6M  [C_0201]  160.66 70.71 180 top
CD76  1U_0201_10V6M  [C_0201]  157.51 51.56 90 top
CD77  1U_0201_10V6M  [C_0201]  162.69 70.71 180 top
CD78  1U_0201_10V6M  [C_0201]  158.38 70.71 180 top
CD79  1U_0201_10V6M  [C_0201]  158.4 52.59 270 top
CD80  1U_0201_10V6M  [C_0201]  162.19 52.04 180 top
CD81  2.2P_0201_50V8B  [C_0201]  167 54.33 0 top
CD83  10U_0402_10V6M  [C_0402]  108.24 54.85 270 top
CD84  10U_0402_10V6M  [C_0402]  121.66 54.94 270 top
CD85  10U_0402_10V6M  [C_0402]  121.64 70.78 270 top
CD86  10U_0402_10V6M  [C_0402]  136.47 67.23 270 top
CD87  10U_0402_10V6M  [C_0402]  141.62 52.42 0 top
CD88  10U_0402_10V6M  [C_0402]  151.18 70.71 180 top
CD89  10U_0402_10V6M  [C_0402]  163.02 52.42 0 top
CD90  10U_0402_10V6M  [C_0402]  164.89 70.71 180 top
CD91  12P_0201_50V8J  [C_0201]  140.22 56.74 180 top
CD303  10U_0402_10V6M  [C_0402]  153.64 55.55 270 top
CD304  10U_0402_10V6M  [C_0402]  140.13 58.77 180 top
CD305  10U_0402_10V6M  [C_0402]  167.09 64.74 0 top
CD306  10U_0402_10V6M  [C_0402]  166.9 59.73 0 top
CD307  10U_0402_10V6M  [C_0402]  140.13 62.08 180 top
CD308  10U_0402_10V6M  [C_0402]  153.64 60.73 90 top
CD309  0.1U_0402_25V6  [C_0402]  83.75 65.7 0 top
CE39  2200P_0402_50V7K  [C_0402]  214.17 68.3 180 top
CE42  0.1U_0201_10V6K  [C_0201]  207.61 65.92 270 bottom
CE43  0.1U_0201_10V6K  [C_0201]  211.62 65.09 90 bottom
CE44  1U_0201_6.3V6M  [C_0201]  212.18 65.11 90 bottom
CE45  0.1U_0201_10V6K  [C_0201]  204.31 60.13 90 top
CE46  10U_0402_6.3V6M  [C_0402]  202.92 57.85 270 top
CE47  22U_0603_6.3V6M  [C_0603]  204.06 62.9 270 top
CE48  0.1U_0201_10V6K  [C_0201]  204.95 62.62 270 top
CE49  0.1U_0201_10V6K  [C_0201]  204.95 60.13 90 top
CE50  0.1U_0201_10V6K  [C_0201]  213.58 57.03 270 bottom
CE51  0.1U_0201_10V6K  [C_0201]  212.95 57.03 270 bottom
CE52  12P_0402_50V8J  [C_0402]  201.84 58.57 90 top
CE53  68P_0402_50V8J  [C_0402]  201.84 57.71 270 top
CE54  0.1U_0201_10V6K  [C_0201]  200.59 66.27 0 top
CE55  100P_0201_50V8J  [C_0201]  192.76 54.93 90 bottom
CE56  0.1U_0201_10V6K  [C_0201]  214.98 59.57 270 bottom
CE57  100P_0201_50V8J  [C_0201]  143.92 26.22 90 bottom
CE58  100P_0201_50V8J  [C_0201]  137.34 68.93 0 bottom
CE60  100P_0201_50V8J  [C_0201]  244.29 13.97 90 top
CE61  0.1U_0402_25V6  [C_0402]  199.44 60.74 180 top
CE63  1U_0201_6.3V6M  [C_0201]  218.84 51.28 0 top
CE64  1U_0201_6.3V6M  [C_0201]  204.97 58.27 180 top
CE65  33P_0201_50V8J  [C_0201]  212.7 69.03 180 top
CE66  10P_0402_50V8J  [C_0402]  206.42 69.06 180 top
CE67  100P_0201_50V8J  [C_0201]  85.57 23.65 90 top
CE68  1U_0201_10V6M  [C_0201]  200.21 63.85 0 top
CE69  100P_0201_50V8J  [C_0201]  210.34 39.51 270 top
CE75  4700P_0402_25V7K  [C_0402]  218.97 60.04 0 top
CE76  2200P_0402_50V7K  [C_0402]  212.39 68.3 180 top
CE79  0.1U_0402_25V6  [C_0402]  218.97 65.89 0 top
CE86  2200P_0402_50V7K  [C_0402]  217.72 68.3 180 top
CE88  0.1U_0201_10V6K  [C_0201]  209.76 55.88 90 bottom
CE89  10P_0402_50V8J  [C_0402]  207.66 69.06 0 top
CE93  2200P_0402_50V7K  [C_0402]  215.95 68.3 180 top
CE104  2.2U_0201_6.3V6M  [C_0201]  202.23 63.09 180 top
CE105  10P_0402_50V8J  [C_0402]  202.1 62.08 180 top
CE106  2200P_0402_50V7K  [C_0402]  209.65 52.37 270 top
CE107  2200P_0402_50V7K  [C_0402]  209.65 54.15 270 top
CE108  0.1U_0201_10V6K  [C_0201]  211.68 54.11 270 top
CE109  10U_0402_10V6M  [C_0402]  212.35 48.89 180 top
CE110  100P_0201_50V8J  [C_0201]  217.55 70.17 0 top
CE312  0.1U_0402_25V6  [C_0402]  84.57 58.82 0 top
CE410  0.1U_0402_25V6  [C_0402]  213.73 26.53 270 top
CE413  0.1U_0402_25V6  [C_0402]  26.14 4.36 270 top
CE429  0.1U_0402_25V6  [C_0402]  268.21 8.19 90 top
CE430  0.1U_0402_25V6  [C_0402]  96.31 50.71 180 top
CE431  0.1U_0402_25V6  [C_0402]  198.85 6.16 180 top
CE432  4700P_0402_25V7K  [C_0402]  204.9 63.85 180 top
CH1  0.1U_0402_10V7K~D  [C_0402]  184.5 52.6 90 top
CH2  0.1U_0402_10V7K~D  [C_0402]  185.39 52.6 90 top
CH3  0.1U_0402_10V7K~D  [C_0402]  186.41 52.6 90 top
CH4  0.1U_0402_10V7K~D  [C_0402]  187.29 52.6 90 top
CH10  10P_0201_50V8J  [C_0201]  179.48 29.46 90 top
CH11  10P_0201_50V8J  [C_0201]  179.48 31.32 270 top
CH12  15P_0201_50V8J  [C_0201]  171.34 52.17 0 top
CH13  15P_0201_50V8J  [C_0201]  169.46 52.17 180 top
CH35  0.1U_0201_10V6K  [C_0201]  235.83 15.09 0 top
CH40  22P_0201_50V8J  [C_0201]  163.7 50.1 90 bottom
CH44  0.1U_0201_10V6K  [C_0201]  225.14 10.65 270 top
CH45  0.1U_0201_10V6K  [C_0201]  225.7 10.65 270 top
CH46  1U_0201_6.3V6K  [C_0201]  177.92 50.39 0 top
CH47  1U_0201_6.3V6K  [C_0201]  170.53 50.68 270 bottom
CH48  0.01U_0402_16V7K  [C_0402]  177.96 48.75 270 top
CH49  0.1U_0201_10V6K  [C_0201]  167.29 50.1 90 top
CH50  56P_0201_25V8J  [C_0201]  164.31 50.1 90 bottom
CH51  56P_0201_25V8J  [C_0201]  163.16 48.14 270 bottom
CH52  0.33U_0201_6.3V6M  [C_0201]  174.23 50.99 90 top
CH53  0.33U_0201_6.3V6M  [C_0201]  174.8 50.99 90 top
CH54  0.33U_0201_6.3V6M  [C_0201]  173.51 50.99 90 top
CH55  0.33U_0201_6.3V6M  [C_0201]  175.94 50.99 90 top
CH56  0.33U_0201_6.3V6M  [C_0201]  176.51 50.99 90 top
CH57  0.33U_0201_6.3V6M  [C_0201]  175.37 50.99 90 top
CM1  0.1U_0201_25V6K  [C_0201]  16.14 58.39 180 top
CM2  0.1U_0201_25V6K  [C_0201]  269.42 57 0 top
CP10  10U_0402_10V6M  [C_0402]  276.32 14.7 180 top
CPD1  0.1U_0201_10V6K  [C_0201]  14.32 27.78 45 bottom
CPD2  220P_0201_25V6K  [C_0201]  19.67 18.69 315 top
CPD3  220P_0201_25V6K  [C_0201]  18.24 17.25 315 top
CPD4  10U_0402_10V6M  [C_0402]  11.09 16.5 135 top
CPD5  10U_0402_10V6M  [C_0402]  9.2 17.41 225 top
CPD6  4.7U_0402_6.3V6M  [C_0402]  17.95 24.14 135 top
CPD7  10U_0402_10V6M  [C_0402]  8.29 21.97 45 top
CPD8  22U_0603_10V6M  [C_0603]  18.89 17.85 315 top
CPD11  0.1U_0201_10V6K  [C_0201]  232.76 11.64 270 bottom
CPD12  220P_0201_25V6K  [C_0201]  282.47 8.38 270 top
CPD13  220P_0201_25V6K  [C_0201]  283.99 8.45 270 top
CPD14  10U_0402_10V6M  [C_0402]  276.32 13.68 180 top
CPD16  4.7U_0402_6.3V6M  [C_0402]  287.1 13.55 0 top
CPD17  10U_0402_10V6M  [C_0402]  283.23 8.45 270 top
CPD18  22U_0603_10V6M  [C_0603]  276.94 16.98 180 top
CPD19  10U_0603_35V6M  [C_0603]  276.05 11.33 90 top
CPD40  10U_0603_35V6M  [C_0603]  12 15.4 315 top
CPD41  1U_0402_25V6K  [C_0402]  274.47 16.22 90 top
CPD42  1U_0402_25V6K  [C_0402]  7.18 17.4 270 top
CPD47  10U_0603_35V6M  [C_0603]  11.15 14.55 315 top
CPD48  10U_0603_35V6M  [C_0603]  274.85 11.33 90 top
CPD49  1U_0402_25V6K  [C_0402]  13.77 13.89 225 top
CPD51  1U_0402_25V6K  [C_0402]  276.99 10.3 180 top
CR1  0.1U_0201_10V6K  [C_0201]  275.84 28.04 0 top
CR2  0.1U_0201_10V6K  [C_0201]  275.84 27.47 0 top
CR3  0.1U_0201_10V6K  [C_0201]  275.84 25.18 0 top
CR4  0.1U_0201_10V6K  [C_0201]  275.84 24.61 0 top
CR5  4.7U_0402_6.3V6M  [C_0402]  280.82 22.2 0 top
CR6  0.1U_0201_10V6K  [C_0201]  277.95 23.34 180 top
CR7  10U_0402_6.3V6M  [C_0402]  279.32 22.2 180 top
CR8  0.1U_0201_10V6K  [C_0201]  279.28 22.96 180 top
CR9  0.1U_0201_10V6K  [C_0201]  281.44 22.96 180 top
CR10  2.2P_0201_50V8C  [C_0201]  284.92 23.34 0 top
CR11  2.2P_0201_50V8C  [C_0201]  284.92 23.98 0 top
CR13  2.2P_0201_50V8C  [C_0201]  284.92 24.74 0 top
CR15  1U_0201_6.3V6M  [C_0201]  283.65 25.37 0 top
CR16  2.2P_0201_50V8C  [C_0201]  284.92 26.01 0 top
CR17  2.2P_0201_50V8C  [C_0201]  284.92 26.64 0 top
CR18  2.2P_0201_50V8C  [C_0201]  284.92 27.28 0 top
CR19  1U_0201_6.3V6M  [C_0201]  283.65 28.68 0 top
CR20  0.1U_0201_10V6K  [C_0201]  281.27 30.29 90 top
CR21  10U_0402_6.3V6M  [C_0402]  274.37 53.38 180 top
CR22  4.7U_0402_6.3V6M  [C_0402]  289.86 42.01 180 top
CR23  4.7U_0402_6.3V6M  [C_0402]  282.04 30.38 90 top
CR24  0.1U_0402_10V7K  [C_0402]  289.86 41.12 180 top
CR25  0.1U_0402_10V7K  [C_0402]  273.45 52.49 0 top
CS1  0.22U_0201_6.3V6M  [C_0201]  190.68 42.52 0 top
CS2  0.22U_0201_6.3V6M  [C_0201]  190.68 43.15 0 top
CS3  0.22U_0201_6.3V6M  [C_0201]  190.68 41.76 0 top
CS4  0.22U_0201_6.3V6M  [C_0201]  190.68 41.12 0 top
CS5  0.22U_0201_6.3V6M  [C_0201]  190.68 40.36 0 top
CS6  0.22U_0201_6.3V6M  [C_0201]  190.68 39.72 0 top
CS7  0.22U_0201_6.3V6M  [C_0201]  190.68 38.33 0 top
CS8  0.22U_0201_6.3V6M  [C_0201]  190.68 38.96 0 top
CS16  0.22U_0201_6.3V6M  [C_0201]  191.26 32.67 90 top
CS17  0.22U_0201_6.3V6M  [C_0201]  190.68 32.67 90 top
CS18  0.22U_0201_6.3V6M  [C_0201]  190.68 34.9 0 top
CS19  0.22U_0201_6.3V6M  [C_0201]  190.68 34.26 0 top
CS20  0.22U_0201_6.3V6M  [C_0201]  190.68 35.53 0 top
CS21  0.22U_0201_6.3V6M  [C_0201]  190.68 36.17 0 top
CS22  0.22U_0201_6.3V6M  [C_0201]  190.68 36.93 0 top
CS23  0.22U_0201_6.3V6M  [C_0201]  190.68 37.57 0 top
CS24  0.22U_0201_6.3V6M  [C_0201]  206.66 15.25 270 bottom
CS25  0.22U_0201_6.3V6M  [C_0201]  207.3 15.25 270 bottom
CS26  0.22U_0201_6.3V6M  [C_0201]  210.22 15.25 270 bottom
CS27  0.22U_0201_6.3V6M  [C_0201]  209.58 15.25 270 bottom
CS89  33P_0201_25V8J  [C_0201]  218.54 2.42 270 bottom
CS90  4.7U_0402_10V6M  [C_0402]  218.04 6.64 180 top
CS91  0.1U_0201_10V6K  [C_0201]  200.35 3.66 180 bottom
CS92  0.01U_0201_16V7  [C_0201]  200.35 3.02 180 bottom
CS93  47P_0201_25V8J  [C_0201]  217.96 2.42 270 bottom
CS94  1U_0201_6.3V6M  [C_0201]  220.82 9.47 270 top
CS95  0.01U_0201_16V7  [C_0201]  216.86 7.4 180 top
CT1  0.22U_0201_6.3V6M  [C_0201]  12.92 40.96 90 top
CT2  0.22U_0201_6.3V6M  [C_0201]  13.49 40.96 90 top
CT3  0.22U_0201_6.3V6M  [C_0201]  11.65 40.96 90 top
CT4  0.22U_0201_6.3V6M  [C_0201]  12.22 40.96 90 top
CT5  0.22U_0201_6.3V6M  [C_0201]  9.68 40.96 90 top
CT6  0.22U_0201_6.3V6M  [C_0201]  9.11 40.96 90 top
CT7  0.22U_0201_6.3V6M  [C_0201]  10.95 40.96 90 top
CT8  0.22U_0201_6.3V6M  [C_0201]  10.38 40.96 90 top
CT9  0.22U_0201_6.3V6M  [C_0201]  281.66 32.83 90 top
CT10  0.22U_0201_6.3V6M  [C_0201]  281.02 32.83 90 top
CT11  0.22U_0201_6.3V6M  [C_0201]  279.75 32.83 90 top
CT12  0.22U_0201_6.3V6M  [C_0201]  280.39 32.83 90 top
CT13  0.22U_0201_6.3V6M  [C_0201]  277.21 32.83 90 top
CT14  0.22U_0201_6.3V6M  [C_0201]  277.85 32.83 90 top
CT15  0.22U_0201_6.3V6M  [C_0201]  279.12 32.83 90 top
CT16  0.22U_0201_6.3V6M  [C_0201]  278.48 32.83 90 top
CT30  0.22U_0201_6.3V6M  [C_0201]  12.36 49.53 90 top
CT31  0.22U_0201_6.3V6M  [C_0201]  11.79 49.53 90 top
CT32  0.22U_0201_6.3V6M  [C_0201]  10.65 49.53 90 top
CT33  0.22U_0201_6.3V6M  [C_0201]  11.22 49.53 90 top
CT34  10U_0603_25V6M  [C_0603]  4.15 13.44 90 top
CT35  0.1U_0201_25V6K  [C_0201]  10.73 55.98 0 top
CT36  0.1U_0201_25V6K  [C_0201]  285.71 65.02 270 top
CT37  10U_0603_25V6M  [C_0603]  272.37 11.52 90 top
CT38  0.22U_0201_6.3V6M  [C_0201]  280.45 41.71 90 top
CT39  0.22U_0201_6.3V6M  [C_0201]  279.88 41.71 90 top
CT40  0.22U_0201_6.3V6M  [C_0201]  278.05 41.71 90 top
CT41  0.22U_0201_6.3V6M  [C_0201]  278.62 41.71 90 top
CT42  27P_0201_25V8  [C_0201]  16.52 47.79 180 top
CT43  27P_0201_25V8  [C_0201]  17.14 47.79 0 top
CT44  27P_0201_25V8  [C_0201]  285.47 39.89 270 top
CT45  27P_0201_25V8  [C_0201]  285.47 40.57 90 top
CT49  1U_0201_6.3V6K  [C_0201]  11.15 46.9 225 bottom
CT50  1U_0201_6.3V6K  [C_0201]  11.06 44.3 180 bottom
CT51  1U_0201_6.3V6K  [C_0201]  11.78 45.65 90 bottom
CT52  1U_0201_6.3V6K  [C_0201]  12.42 45.65 90 bottom
CT53  1U_0201_6.3V6K  [C_0201]  12.45 44.3 180 bottom
CT54  1U_0201_6.3V6K  [C_0201]  12.45 46.84 180 bottom
CT55  47U_0603_6.3V6M  [C_0603]  16.35 40.11 0 top
CT56  18P_0201_25V8J  [C_0201]  15.4 40.96 90 top
CT57  1U_0201_6.3V6K  [C_0201]  11.06 44.93 180 bottom
CT58  1U_0201_6.3V6K  [C_0201]  13.88 43.32 270 bottom
CT59  1U_0201_6.3V6K  [C_0201]  13.05 44.21 270 bottom
CT60  1U_0201_6.3V6K  [C_0201]  14.54 45.82 0 bottom
CT61  1U_0201_6.3V6K  [C_0201]  11.06 45.57 180 bottom
CT62  1U_0201_6.3V6K  [C_0201]  16.23 44.33 270 top
CT63  1U_0201_6.3V6K  [C_0201]  15.65 44.33 270 top
CT64  1U_0201_6.3V6K  [C_0201]  13.05 46.29 90 bottom
CT68  1U_0201_6.3V6K  [C_0201]  279.09 36.93 180 bottom
CT69  1U_0201_6.3V6K  [C_0201]  281.66 35.57 270 bottom
CT70  1U_0201_6.3V6K  [C_0201]  279.09 37.5 180 bottom
CT71  1U_0201_6.3V6K  [C_0201]  284.27 36.26 270 top
CT72  1U_0201_6.3V6K  [C_0201]  283.69 36.26 270 top
CT73  1U_0201_6.3V6K  [C_0201]  280.39 36.33 270 bottom
CT74  1U_0201_6.3V6K  [C_0201]  278.89 36.3 0 bottom
CT75  1U_0201_6.3V6K  [C_0201]  280.32 37.78 90 bottom
CT76  1U_0201_6.3V6K  [C_0201]  279.69 37.78 90 bottom
CT77  1U_0201_6.3V6K  [C_0201]  279.03 38.96 90 bottom
CT78  1U_0201_6.3V6K  [C_0201]  280.3 38.96 180 bottom
CT79  47U_0603_6.3V6M  [C_0603]  285.59 32.17 90 top
CT80  18P_0201_25V8J  [C_0201]  285.53 31.38 270 top
CT81  1U_0201_6.3V6K  [C_0201]  281.66 38.42 90 bottom
CT82  1U_0201_6.3V6K  [C_0201]  281.02 36.33 270 bottom
CT84  1U_0201_6.3V6K  [C_0201]  281.57 37.57 180 bottom
CT200  10U_0402_10V6M  [C_0402]  15.89 45.67 0 top
CT201  10U_0402_10V6M  [C_0402]  284.25 37.31 0 top
CT206  100P_0201_50V8J  [C_0201]  12.78 61.16 270 top
CT207  100P_0201_50V8J  [C_0201]  13.88 66.99 90 top
CT210  470P_0402_50V7K  [C_0402]  288.56 31.98 0 top
CT211  1U_0201_6.3V6K  [C_0201]  287.62 26.45 270 top
CT212  0.1U_0201_10V6K  [C_0201]  289.06 33.5 180 top
CT302  18P_0201_25V8J  [C_0201]  13.62 46.29 90 bottom
CT303  10U_0402_10V6M  [C_0402]  14.02 37.79 180 top
CT304  10U_0402_10V6M  [C_0402]  286.91 36.68 0 top
CT305  18P_0201_25V8J  [C_0201]  280.89 38.42 90 bottom
CT306  100P_0201_50V8J  [C_0201]  273.03 62.79 0 bottom
CT307  100P_0201_50V8J  [C_0201]  272.22 62.23 180 bottom
CT310  0.1U_0201_25V6K  [C_0201]  9.07 61.82 0 bottom
CT311  0.1U_0201_25V6K  [C_0201]  9.07 63.35 0 bottom
CT312  0.1U_0201_25V6K  [C_0201]  9.07 61.25 0 bottom
CT313  0.1U_0201_25V6K  [C_0201]  9.07 63.92 0 bottom
CT314  0.1U_0201_25V6K  [C_0201]  280.79 73.73 45 top
CT315  0.1U_0201_25V6K  [C_0201]  283.08 74.97 0 bottom
CT316  0.1U_0201_25V6K  [C_0201]  282.95 72.62 0 bottom
CT317  0.1U_0201_25V6K  [C_0201]  280.8 71.52 45 top
CT318  1U_0402_25V6K  [C_0402]  5.23 14.79 270 top
CT319  1U_0402_25V6K  [C_0402]  6.22 17.4 270 top
CT325  1U_0402_25V6K  [C_0402]  271.74 16.4 90 top
CT338  2200P_0201_25V7K  [C_0201]  4.86 16.53 90 bottom
CT339  0.01U_0201_25V6K  [C_0201]  6 16.53 90 bottom
CT340  0.1U_0201_25V6K  [C_0201]  6.57 16.53 90 bottom
CT341  100P_0201_50V8J  [C_0201]  5.43 16.53 90 bottom
CT342  2200P_0201_25V7K  [C_0201]  8.92 19.7 45 bottom
CT343  1000P_0201_50V7K  [C_0201]  10.69 17.94 45 bottom
CT344  100P_0201_50V8J  [C_0201]  8.47 20.15 45 bottom
CT345  0.1U_0201_25V6K  [C_0201]  9.37 19.26 45 bottom
CT346  1U_0402_25V6K  [C_0402]  8.3 19.41 135 top
CT347  10U_0603_25V6M  [C_0603]  7.4 53.06 0 top
CT348  2200P_0201_25V7K  [C_0201]  268.56 12.19 270 top
CT349  0.01U_0201_25V6K  [C_0201]  269.2 12.19 270 top
CT350  0.1U_0201_25V6K  [C_0201]  269.83 12.19 270 top
CT351  100P_0201_50V8J  [C_0201]  270.47 12.19 270 top
CT352  2200P_0201_25V7K  [C_0201]  268.82 16.5 90 top
CT353  1000P_0201_50V7K  [C_0201]  270.09 16.5 90 top
CT354  100P_0201_50V8J  [C_0201]  272.05 14.8 270 top
CT355  0.1U_0201_25V6K  [C_0201]  269.45 16.5 90 top
CT356  1U_0402_25V6K  [C_0402]  270.85 16.4 90 top
CT357  10U_0603_25V6M  [C_0603]  283.55 63.71 0 top
